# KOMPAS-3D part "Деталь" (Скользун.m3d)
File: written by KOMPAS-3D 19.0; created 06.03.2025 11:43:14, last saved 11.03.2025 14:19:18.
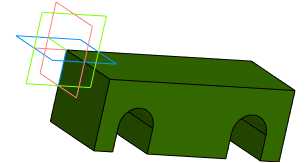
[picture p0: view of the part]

Document properties: Автор: user-2; Полное имя файла: D:\ОПР Врацкий\_Работы 2025\3D\Скользун.m3d

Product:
- Part/product: Деталь
    Масса: 2.53102

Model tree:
1. Эскиз:1
2. Элемент выдавливания:1
     Расстояние 2 = 60
3. Эскиз:2  (with: Элемент выдавливания:1)
4. Элемент выдавливания:2
     Расстояние 2 = 15
5. Эскиз:3  (with: Элемент выдавливания:1)
6. Элемент выдавливания:3
     Расстояние 2 = 11
7. Эскиз:4  (with: Элемент выдавливания:1)
8. Элемент выдавливания:4
     Расстояние 2 = 15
